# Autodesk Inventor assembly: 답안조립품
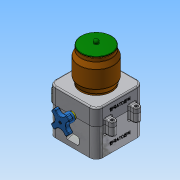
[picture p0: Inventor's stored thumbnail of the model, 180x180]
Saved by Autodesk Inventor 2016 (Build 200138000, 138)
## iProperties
Created: 2018-01
Part Number: 답안조립품
Material: 일반
Document SubType Name: Assembly
Designer: Administrator
Author: Administrator
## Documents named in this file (9)
- C:\Users\Administrator\Desktop\480107V1038\답안조립품.iam
- C:\Users\Administrator\Desktop\480107V1038\본체.ipt
- C:\Users\Administrator\Desktop\480107V1038\핸들축.ipt
- C:\Users\Administrator\Desktop\480107V1038\핸들.ipt
- C:\Users\Administrator\Desktop\480107V1038\본체커버.ipt
- C:\Users\Administrator\Desktop\480107V1038\용기.ipt
- C:\Users\Administrator\Desktop\480107V1038\용기캡.ipt
- C:\Users\Administrator\Desktop\480107V1038\볼트 M3x12.ipt
- C:\Users\Administrator\Desktop\480107V1038\볼트 M4x12.ipt
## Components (2 placed, 2 different names)
1. 핸들축:1
2. 핸들:1
